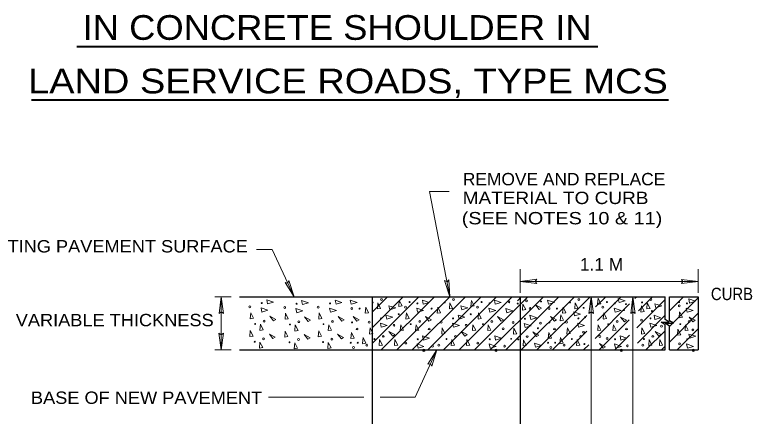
# Model space of a CAD drawing. Extents: x 312583 to 312854, y 144419 to 144597.
# Drawn here: x 312628.97 to 312674.34, y 144455.11 to 144479.79 of the extents above; entities that cross this region are included whole.
import ezdxf
from ezdxf.enums import TextEntityAlignment as Align

# ---------------------------------------------------------------- set-up
doc = ezdxf.new("R2010")
doc.units = 0
doc.header["$LTSCALE"] = 0.3
doc.header["$PDMODE"] = 32
doc.header["$PDSIZE"] = 0.15
doc.layers.add('1', color=7, linetype='Continuous', lineweight=13)

msp = doc.modelspace()

# ---------------------------------------------------------------- linework, layer by layer
at = {"layer": '1', "lineweight": 40}
for p, q in [((312632.7943, 144477.8512), (312664.8483, 144477.8512)), ((312629.9918, 144474.5584), (312669.1922, 144474.5584))]:
    msp.add_line(p, q, dxfattribs=at)
at = {"layer": '1'}
for p, q in [((312644.8091, 144465.3641), (312643.8508, 144465.3641)), ((312644.8091, 144465.3641), (312646.1585, 144462.4584)), ((312660.0581, 144464.1604), (312660.0581, 144462.6884)), ((312671.0138, 144464.1604), (312671.0138, 144462.6884)), ((312660.0581, 144463.4014), (312671.0138, 144463.4014)), ((312642.2868, 144462.4584), (312641.2748, 144462.4584)), ((312641.6735, 144462.4584), (312641.6735, 144459.1848)), ((312650.9501, 144459.5834), (312653.8251, 144462.4584)), ((312650.9501, 144460.5418), (312652.8668, 144462.4584)), ((312650.9501, 144461.5001), (312651.9085, 144462.4584)), ((312651.5098, 144459.1848), (312654.7835, 144462.4584)), ((312652.4681, 144459.1848), (312655.7418, 144462.4584)), ((312653.4265, 144459.1848), (312656.7001, 144462.4584)), ((312654.3848, 144459.1848), (312657.6585, 144462.4584)), ((312655.3431, 144459.1848), (312658.6168, 144462.4584)), ((312656.3015, 144459.1848), (312659.5751, 144462.4584)), ((312657.2598, 144459.1848), (312660.5335, 144462.4584)), ((312658.2181, 144459.1848), (312661.4918, 144462.4584)), ((312659.1765, 144459.1848), (312662.4501, 144462.4584)), ((312659.8895, 144462.2131), (312660.1348, 144462.4584)), ((312660.1348, 144459.1848), (312663.4085, 144462.4584)), ((312661.0931, 144459.1848), (312664.3668, 144462.4584)), ((312664.4281, 144462.4584), (312664.4281, 144440.1484)), ((312664.6965, 144461.8298), (312665.3251, 144462.4584)), ((312664.8191, 144460.9941), (312666.2835, 144462.4584)), ((312667.0041, 144462.4584), (312667.0041, 144433.4478)), ((312667.1191, 144462.3434), (312667.2418, 144462.4584)), ((312667.2495, 144460.5494), (312668.9821, 144462.2821)), ((312667.3415, 144461.5998), (312668.2001, 144462.4584)), ((312669.2428, 144461.5844), (312670.1168, 144462.4584)), ((312669.2428, 144460.6261), (312671.0138, 144462.3971)), ((312664.6811, 144459.8978), (312666.7971, 144462.0138)), ((312662.0515, 144459.1848), (312664.1675, 144461.3084)), ((312667.2725, 144459.6141), (312668.9821, 144461.3238)), ((312669.2428, 144459.6678), (312671.0138, 144461.4388)), ((312664.9265, 144459.1848), (312666.7741, 144461.0324)), ((312667.8015, 144459.1848), (312668.9821, 144460.3654)), ((312669.7181, 144459.1848), (312671.0138, 144460.4804)), ((312663.0098, 144459.1848), (312664.1598, 144460.3348)), ((312665.8848, 144459.1848), (312666.7971, 144460.1048)), ((312663.9681, 144459.1848), (312664.2825, 144459.4991)), ((312642.2868, 144459.1848), (312641.2748, 144459.1848)), ((312653.5951, 144456.2791), (312654.9445, 144459.1848)), ((312668.7598, 144459.1848), (312668.9591, 144459.3918)), ((312650.4365, 144456.2791), (312644.5868, 144456.2791)), ((312653.5951, 144456.2791), (312651.4485, 144456.2791))]:
    msp.add_line(p, q, dxfattribs=at)
at = {"layer": '1', "lineweight": 25}
for p, q in [((312642.8005, 144462.4584), (312668.9821, 144462.4584)), ((312646.1585, 144462.4584), (312661.0165, 144462.4584)), ((312650.9501, 144462.4584), (312650.9501, 144433.4478)), ((312660.0581, 144462.4584), (312660.0581, 144459.1848)), ((312669.2428, 144462.4584), (312671.0138, 144462.4584)), ((312671.0138, 144462.4584), (312671.0138, 144459.1848)), ((312642.8005, 144459.1848), (312649.4321, 144459.1848)), ((312649.4321, 144459.1848), (312668.9821, 144459.1848)), ((312660.0581, 144459.1848), (312660.0581, 144433.4478)), ((312669.2428, 144459.1848), (312671.0138, 144459.1848))]:
    msp.add_line(p, q, dxfattribs=at)
at = {"layer": '1'}
for points in [[(312655.6958, 144468.9214), (312654.4921, 144468.9214), (312655.7418, 144462.4584)], [(312652.5985, 144461.8681), (312652.6215, 144462.2361), (312652.7978, 144461.8988), (312652.5985, 144461.8604)], [(312657.0298, 144461.8681), (312657.0605, 144462.2361), (312657.2291, 144461.8988), (312657.0298, 144461.8604)], [(312664.8268, 144461.9984), (312664.8575, 144462.3664), (312665.0261, 144462.0214), (312664.8268, 144461.9908)], [(312650.5285, 144461.4464), (312650.5591, 144461.8144), (312650.7278, 144461.4771), (312650.5361, 144461.4388)], [(312651.2798, 144461.7148), (312651.3028, 144462.0828), (312651.4791, 144461.7454), (312651.2798, 144461.7071)], [(312654.9675, 144461.4464), (312654.9981, 144461.8144), (312655.1668, 144461.4771), (312654.9675, 144461.4388)], [(312655.7111, 144461.7148), (312655.7418, 144462.0828), (312655.9105, 144461.7454), (312655.7111, 144461.7071)], [(312660.2038, 144461.6381), (312660.2345, 144462.0061), (312660.4031, 144461.6688), (312660.2038, 144461.6304)], [(312662.6725, 144461.4464), (312662.7031, 144461.8144), (312662.8718, 144461.4771), (312662.6801, 144461.4388)], [(312663.4238, 144461.7148), (312663.4468, 144462.0828), (312663.6231, 144461.7454), (312663.4238, 144461.7071)], [(312667.4948, 144461.5231), (312667.5255, 144461.8911), (312667.6941, 144461.5461), (312667.4948, 144461.5154)], [(312667.8551, 144461.7148), (312667.8858, 144462.0828), (312668.0545, 144461.7454), (312667.8551, 144461.7071)], [(312647.6688, 144461.0938), (312647.6995, 144461.4618), (312647.8681, 144461.1168), (312647.6688, 144461.0861)], [(312653.0355, 144461.0938), (312653.0661, 144461.4618), (312653.2348, 144461.1168), (312653.0355, 144461.0861)], [(312657.4745, 144461.0938), (312657.4975, 144461.4618), (312657.6661, 144461.1168), (312657.4745, 144461.0861)], [(312665.1795, 144461.0938), (312665.2101, 144461.4618), (312665.3788, 144461.1168), (312665.1795, 144461.0861)], [(312669.8408, 144461.1628), (312669.8715, 144461.5308), (312670.0401, 144461.1934), (312669.8485, 144461.1551)], [(312644.0501, 144460.3961), (312644.0808, 144460.7641), (312644.2495, 144460.4268), (312644.0578, 144460.3884)], [(312646.1968, 144460.3578), (312646.2275, 144460.7258), (312646.3961, 144460.3884), (312646.1968, 144460.3501)], [(312647.6381, 144459.9974), (312647.6688, 144460.3654), (312647.8375, 144460.0281), (312647.6381, 144459.9898)], [(312650.7968, 144460.1738), (312650.8275, 144460.5418), (312650.9961, 144460.2044), (312650.7968, 144460.1661)], [(312655.2358, 144460.1738), (312655.2665, 144460.5418), (312655.4351, 144460.2044), (312655.2358, 144460.1661)], [(312659.6518, 144460.1584), (312659.6825, 144460.5188), (312659.8511, 144460.1814), (312659.6518, 144460.1508)], [(312662.9408, 144460.1738), (312662.9715, 144460.5418), (312663.1401, 144460.2044), (312662.9408, 144460.1661)], [(312667.5255, 144460.1738), (312667.5561, 144460.5418), (312667.7248, 144460.2044), (312667.5255, 144460.1661)], [(312669.7488, 144460.0971), (312669.7718, 144460.4651), (312669.9481, 144460.1201), (312669.7488, 144460.0894)], [(312649.6468, 144459.8978), (312649.6775, 144460.2581), (312649.8461, 144459.9208), (312649.6468, 144459.8901)], [(312650.3675, 144459.5758), (312650.3981, 144459.9438), (312650.5668, 144459.5988), (312650.3675, 144459.5681)], [(312661.7908, 144459.8978), (312661.8215, 144460.2581), (312661.9901, 144459.9208), (312661.7908, 144459.8901)], [(312662.5115, 144459.5758), (312662.5421, 144459.9438), (312662.7108, 144459.5988), (312662.5115, 144459.5681)], [(312644.0271, 144459.2998), (312644.0578, 144459.6678), (312644.2265, 144459.3304), (312644.0271, 144459.2921)], [(312646.1661, 144459.2614), (312646.1968, 144459.6294), (312646.3655, 144459.2921), (312646.1661, 144459.2538)], [(312648.2361, 144459.2844), (312648.2591, 144459.6448), (312648.4278, 144459.3074), (312648.2361, 144459.2768)], [(312651.3948, 144459.4608), (312651.4178, 144459.8288), (312651.5865, 144459.4838), (312651.3948, 144459.4531)], [(312652.3301, 144459.4608), (312652.3608, 144459.8211), (312652.5295, 144459.4838), (312652.3301, 144459.4531)], [(312655.8261, 144459.4608), (312655.8568, 144459.8288), (312656.0255, 144459.4838), (312655.8261, 144459.4531)], [(312656.7615, 144459.4608), (312656.7921, 144459.8211), (312656.9608, 144459.4838), (312656.7615, 144459.4531)], [(312663.5388, 144459.4608), (312663.5618, 144459.8288), (312663.7305, 144459.4838), (312663.5388, 144459.4531)], [(312667.9701, 144459.4608), (312668.0008, 144459.8288), (312668.1695, 144459.4838), (312667.9701, 144459.4531)], [(312668.6295, 144459.4608), (312668.6525, 144459.8211), (312668.8211, 144459.4838), (312668.6295, 144459.4531)]]:
    msp.add_lwpolyline(points, dxfattribs=at)
for points in [[(312661.0931, 144463.2711), (312660.0581, 144463.4014), (312661.0931, 144463.5394), (312660.9858, 144463.4014)], [(312669.9788, 144463.5241), (312671.0138, 144463.4014), (312669.9788, 144463.2634), (312670.0785, 144463.4014)], [(312645.8365, 144463.4551), (312646.1585, 144462.4584), (312645.5988, 144463.3401), (312645.7675, 144463.3018)], [(312655.6651, 144463.5011), (312655.7418, 144462.4584), (312655.4121, 144463.4474), (312655.5655, 144463.3784)], [(312641.5508, 144461.4234), (312641.6735, 144462.4584), (312641.8115, 144461.4234), (312641.6735, 144461.5308)], [(312644.4718, 144462.2668), (312644.5255, 144462.0138), (312644.8935, 144462.1288)], [(312646.6108, 144462.2284), (312646.6645, 144461.9754), (312647.0325, 144462.0904)], [(312648.6731, 144462.2514), (312648.7345, 144461.9984), (312649.1025, 144462.1058)], [(312649.6085, 144462.2514), (312649.6621, 144461.9984), (312650.0301, 144462.1058)], [(312654.0475, 144462.2514), (312654.1011, 144461.9984), (312654.4691, 144462.1058)], [(312658.4788, 144462.2514), (312658.5325, 144461.9984), (312658.9005, 144462.1058)], [(312661.7525, 144462.2514), (312661.8061, 144461.9984), (312662.1741, 144462.1058)], [(312664.2978, 144461.4234), (312664.4281, 144462.4584), (312664.5661, 144461.4234), (312664.4281, 144461.5308)], [(312666.0918, 144462.3588), (312666.1455, 144462.1058), (312666.5135, 144462.2131)], [(312666.8815, 144461.4234), (312667.0041, 144462.4584), (312667.1421, 144461.4234), (312667.0041, 144461.5308)], [(312670.4311, 144462.3204), (312670.4848, 144462.0674), (312670.8528, 144462.1824)], [(312644.1268, 144461.7684), (312644.1805, 144461.5154), (312644.5485, 144461.6304)], [(312646.2658, 144461.7301), (312646.3271, 144461.4771), (312646.6951, 144461.5921)], [(312648.3358, 144461.7531), (312648.3895, 144461.5001), (312648.7575, 144461.6074)], [(312651.9775, 144461.9064), (312652.0388, 144461.6534), (312652.4068, 144461.7684)], [(312653.7025, 144461.7531), (312653.7561, 144461.5001), (312654.1241, 144461.6074)], [(312656.4165, 144461.9064), (312656.4701, 144461.6534), (312656.8381, 144461.7684)], [(312658.1338, 144461.7531), (312658.1951, 144461.5001), (312658.5631, 144461.6074)], [(312659.1841, 144461.7378), (312659.2455, 144461.4771), (312659.6135, 144461.5921)], [(312661.3691, 144461.7531), (312661.0011, 144461.9524), (312661.2235, 144461.6688)], [(312665.8465, 144461.7531), (312665.9001, 144461.5001), (312666.2681, 144461.6074)], [(312668.3458, 144462.0291), (312668.4071, 144461.7761), (312668.7751, 144461.8911)], [(312670.2778, 144461.7531), (312670.3391, 144461.5001), (312670.7071, 144461.6074)], [(312643.4598, 144461.1091), (312643.4905, 144461.4771), (312643.6591, 144461.1398)], [(312645.0238, 144461.0631), (312644.6558, 144461.2624), (312644.8858, 144460.9788)], [(312645.6065, 144461.0708), (312645.6295, 144461.4388), (312645.7981, 144461.1014)], [(312651.8088, 144461.3314), (312651.8625, 144461.0784), (312652.2305, 144461.1934)], [(312656.2401, 144461.3314), (312656.3015, 144461.0784), (312656.6695, 144461.1934)], [(312660.6561, 144461.3161), (312660.7175, 144461.0554), (312661.0855, 144461.1704)], [(312662.5268, 144460.9864), (312662.5575, 144461.3544), (312662.7261, 144461.0171)], [(312663.3625, 144461.5384), (312663.4161, 144461.2778), (312663.7841, 144461.3928)], [(312668.2998, 144461.3161), (312668.3535, 144461.0631), (312668.7215, 144461.1704)], [(312647.1628, 144461.0248), (312646.7948, 144461.2241), (312647.0248, 144460.9404)], [(312649.2328, 144461.0478), (312648.8648, 144461.2394), (312649.0871, 144460.9634)], [(312650.1605, 144461.0478), (312649.7925, 144461.2394), (312650.0225, 144460.9634)], [(312651.4638, 144460.8331), (312651.5175, 144460.5801), (312651.8855, 144460.6951)], [(312654.5995, 144461.0478), (312654.2315, 144461.2394), (312654.4538, 144460.9634)], [(312655.9028, 144460.8331), (312655.9565, 144460.5801), (312656.3245, 144460.6951)], [(312659.0308, 144461.0478), (312658.6628, 144461.2394), (312658.8928, 144460.9634)], [(312660.3188, 144460.8178), (312660.3725, 144460.5571), (312660.7405, 144460.6721)], [(312662.3045, 144461.0478), (312661.9365, 144461.2394), (312662.1665, 144460.9634)], [(312663.6078, 144460.8331), (312663.6615, 144460.5801), (312664.0295, 144460.6951)], [(312666.6131, 144461.0171), (312666.2451, 144461.2088), (312666.4751, 144460.9251)], [(312668.0468, 144460.8331), (312668.1005, 144460.5801), (312668.4685, 144460.6951)], [(312670.8298, 144461.0094), (312670.4618, 144461.2011), (312670.6918, 144460.9251)], [(312643.4368, 144460.0128), (312643.4598, 144460.3808), (312643.6361, 144460.0434)], [(312645.5758, 144459.9744), (312645.6065, 144460.3424), (312645.7751, 144460.0051)], [(312648.2591, 144460.3731), (312648.2898, 144460.7411), (312648.4585, 144460.4038)], [(312652.6905, 144460.3731), (312652.7211, 144460.7411), (312652.8898, 144460.4038)], [(312653.6258, 144460.3731), (312653.6565, 144460.7411), (312653.8251, 144460.4038)], [(312657.1295, 144460.3731), (312657.1525, 144460.7411), (312657.3288, 144460.4038)], [(312658.0648, 144460.3731), (312658.0955, 144460.7411), (312658.2641, 144460.4038)], [(312664.8345, 144460.3731), (312664.8651, 144460.7411), (312665.0338, 144460.4038)], [(312665.7698, 144460.3731), (312665.8005, 144460.7411), (312665.9691, 144460.4038)], [(312670.2088, 144460.3731), (312670.2395, 144460.7411), (312670.4081, 144460.4038)], [(312641.8038, 144460.2198), (312641.6735, 144459.1848), (312641.5355, 144460.2198), (312641.6735, 144460.1201)], [(312645.0008, 144459.9668), (312644.6328, 144460.1661), (312644.8551, 144459.8824)], [(312647.1398, 144459.9284), (312646.7718, 144460.1278), (312646.9941, 144459.8441)], [(312649.2021, 144459.9514), (312648.8341, 144460.1508), (312649.0641, 144459.8671)], [(312652.3608, 144460.1278), (312651.9928, 144460.3271), (312652.2228, 144460.0434)], [(312654.0628, 144460.0511), (312654.1165, 144459.7981), (312654.4845, 144459.9054)], [(312656.7998, 144460.1278), (312656.4318, 144460.3271), (312656.6541, 144460.0434)], [(312658.5018, 144460.0511), (312658.5555, 144459.7981), (312658.9235, 144459.9054)], [(312661.2158, 144460.1048), (312660.8478, 144460.3041), (312661.0701, 144460.0204)], [(312666.2068, 144460.0511), (312666.2605, 144459.7981), (312666.6285, 144459.9054)], [(312668.7291, 144460.1278), (312668.3611, 144460.3271), (312668.5911, 144460.0434)], [(312670.4388, 144460.1661), (312670.5001, 144459.9131), (312670.8681, 144460.0281)], [(312653.7178, 144459.5528), (312653.7791, 144459.2998), (312654.1471, 144459.4071)], [(312658.1568, 144459.5528), (312658.2105, 144459.2998), (312658.5785, 144459.4071)], [(312660.2421, 144459.4378), (312660.2728, 144459.8058), (312660.4415, 144459.4684)], [(312660.9475, 144459.6141), (312661.0011, 144459.3534), (312661.3691, 144459.4684)], [(312665.3098, 144459.3841), (312664.9418, 144459.5834), (312665.1641, 144459.2998)], [(312665.8618, 144459.5528), (312665.9231, 144459.2998), (312666.2911, 144459.4071)], [(312670.3008, 144459.5528), (312670.3545, 144459.2998), (312670.7225, 144459.4071)], [(312654.6225, 144458.1958), (312654.9445, 144459.1848), (312654.3848, 144458.3108), (312654.5535, 144458.3414)]]:
    msp.add_lwpolyline(points, close=True, dxfattribs=at)
at = {"layer": '1', "lineweight": 25}
for points in [[(312668.9821, 144459.1848), (312668.9821, 144460.7334), (312668.7291, 144460.9021), (312669.2351, 144460.9021), (312668.9821, 144461.0631), (312668.9821, 144462.4584)], [(312669.2428, 144459.1848), (312669.2428, 144460.6568), (312668.9898, 144460.8254), (312669.4958, 144460.8254), (312669.2428, 144460.9864), (312669.2428, 144462.4584)]]:
    msp.add_lwpolyline(points, dxfattribs=at)
at = {"layer": '1'}
for centre, radius in [((312651.5309, 144462.2802), 0.0565), ((312653.2588, 144462.1288), 0.0288), ((312655.966, 144462.2802), 0.0565), ((312657.6939, 144462.1288), 0.0288), ((312659.3768, 144462.1384), 0.0565), ((312660.4587, 144462.2035), 0.0565), ((312661.3461, 144462.1671), 0.0288), ((312663.6749, 144462.2802), 0.0565), ((312665.4028, 144462.1288), 0.0288), ((312668.1101, 144462.2802), 0.0565), ((312669.8379, 144462.1288), 0.0288), ((312643.4349, 144461.8326), 0.0565), ((312644.1651, 144462.0665), 0.0288), ((312645.5768, 144461.7943), 0.0565), ((312646.307, 144462.0281), 0.0288), ((312647.641, 144461.8135), 0.0565), ((312648.3713, 144462.0473), 0.0288), ((312649.6976, 144461.7301), 0.0565), ((312650.1815, 144461.7272), 0.0288), ((312650.9837, 144462.1096), 0.0288), ((312653.0096, 144461.8135), 0.0565), ((312653.7398, 144462.0473), 0.0288), ((312654.6167, 144461.7272), 0.0288), ((312655.4188, 144462.1096), 0.0288), ((312657.4448, 144461.8135), 0.0565), ((312658.175, 144462.0473), 0.0288), ((312659.9115, 144462.0329), 0.0288), ((312660.6686, 144461.7445), 0.0565), ((312661.8416, 144461.7301), 0.0565), ((312662.3256, 144461.7272), 0.0288), ((312663.1277, 144462.1096), 0.0288), ((312663.9691, 144461.778), 0.0288), ((312665.1536, 144461.8135), 0.0565), ((312665.8838, 144462.0473), 0.0288), ((312666.57, 144462.0032), 0.0288), ((312667.5628, 144462.1096), 0.0288), ((312669.8533, 144461.9016), 0.0565), ((312670.319, 144462.0473), 0.0288), ((312652.5898, 144461.3832), 0.0288), ((312657.025, 144461.3832), 0.0288), ((312666.4502, 144461.641), 0.0288), ((312668.1656, 144461.5777), 0.0288), ((312643.7598, 144460.79), 0.0288), ((312644.307, 144460.9606), 0.0565), ((312646.4488, 144460.9222), 0.0565), ((312647.9659, 144460.7708), 0.0288), ((312648.5131, 144460.9414), 0.0565), ((312649.7187, 144460.8801), 0.0288), ((312650.7728, 144460.8954), 0.0565), ((312651.5031, 144461.1292), 0.0288), ((312653.3345, 144460.7708), 0.0288), ((312653.8817, 144460.9414), 0.0565), ((312655.208, 144460.8954), 0.0565), ((312655.9383, 144461.1292), 0.0288), ((312657.7696, 144460.7708), 0.0288), ((312658.3168, 144460.9414), 0.0565), ((312659.625, 144460.8762), 0.0565), ((312660.3552, 144461.1101), 0.0288), ((312661.3068, 144460.8379), 0.0565), ((312661.8627, 144460.8801), 0.0288), ((312662.9168, 144460.8954), 0.0565), ((312663.6471, 144461.1292), 0.0288), ((312664.0544, 144461.1992), 0.0288), ((312665.4785, 144460.7708), 0.0288), ((312666.0257, 144460.9414), 0.0565), ((312667.5341, 144461.0133), 0.0565), ((312668.0823, 144461.1292), 0.0288), ((312669.9136, 144460.7708), 0.0288), ((312670.4608, 144460.9414), 0.0565), ((312645.9016, 144460.7516), 0.0288), ((312650.0273, 144460.4747), 0.0565), ((312652.3023, 144460.7037), 0.0565), ((312654.4624, 144460.4747), 0.0565), ((312656.7375, 144460.7037), 0.0565), ((312659.0136, 144460.4939), 0.0565), ((312661.1583, 144460.5169), 0.0288), ((312662.1713, 144460.4747), 0.0565), ((312666.6064, 144460.4747), 0.0565), ((312668.7579, 144460.651), 0.0565), ((312670.6947, 144460.4162), 0.0565), ((312644.2801, 144459.8652), 0.0565), ((312648.4863, 144459.846), 0.0565), ((312651.6449, 144460.0233), 0.0565), ((312656.0801, 144460.0233), 0.0565), ((312659.5109, 144459.8719), 0.0288), ((312660.4971, 144460.0041), 0.0565), ((312663.7889, 144460.0233), 0.0565), ((312663.9566, 144460.2706), 0.0565), ((312664.9638, 144460.0137), 0.0565), ((312665.4085, 144459.8911), 0.0565), ((312668.2241, 144460.0233), 0.0565), ((312643.7329, 144459.6946), 0.0288), ((312645.8748, 144459.6563), 0.0288), ((312646.422, 144459.8269), 0.0565), ((312647.939, 144459.6754), 0.0288), ((312649.6391, 144459.6285), 0.0288), ((312650.0713, 144459.6285), 0.0288), ((312650.6205, 144459.4799), 0.0565), ((312651.0977, 144459.8527), 0.0288), ((312653.0288, 144459.6131), 0.0565), ((312653.759, 144459.847), 0.0288), ((312654.6742, 144459.4224), 0.0565), ((312655.0556, 144459.4799), 0.0565), ((312655.5329, 144459.8527), 0.0288), ((312657.4639, 144459.6131), 0.0565), ((312658.1942, 144459.847), 0.0288), ((312659.1094, 144459.4224), 0.0565), ((312659.9498, 144459.8336), 0.0288), ((312661.7831, 144459.6285), 0.0288), ((312662.2153, 144459.6285), 0.0288), ((312662.7645, 144459.4799), 0.0565), ((312663.2417, 144459.8527), 0.0288), ((312664.016, 144459.5508), 0.0288), ((312665.903, 144459.847), 0.0288), ((312666.6572, 144459.4435), 0.0565), ((312667.606, 144459.4799), 0.0565), ((312667.6769, 144459.8527), 0.0288), ((312669.8724, 144459.5604), 0.0565), ((312670.3382, 144459.847), 0.0288), ((312649.8097, 144459.3391), 0.0565), ((312661.9537, 144459.3391), 0.0565)]:
    msp.add_circle(centre, radius, dxfattribs=at)
for p in [(312654.1395, 144459.1694), (312658.5785, 144459.1694), (312666.2835, 144459.1694), (312670.7225, 144459.1694)]:
    msp.add_point(p, dxfattribs=at)

# ---------------------------------------------------------------- texts
for s, width, p in [('IN CONCRETE SHOULDER IN', 1.1, (312648.8038, 144478.2522)), ('LAND SERVICE ROADS, TYPE MCS', 1.15, (312649.4673, 144474.9595))]:
    msp.add_text(s, height=1.52, dxfattribs=dict(at, width=width)).set_placement(p, align=Align.CENTER)
for s, width, p in [('REMOVE AND REPLACE', 1.05, (312656.5381, 144469.3088)), ('MATERIAL TO CURB', 1.15, (312656.5268, 144468.1557)), ('(SEE NOTES 10 & 11)', 1.2, (312656.4708, 144466.9083)), ('EXISTING PAVEMENT SURFACE', 1.1, (312625.9796, 144465.1801)), ('1.1 M', 1.05, (312663.7361, 144464.0708)), ('CURB', 0.9, (312671.7977, 144462.2504)), ('VARIABLE THICKNESS', 1.1, (312629.0331, 144460.6445)), ('BASE OF NEW PAVEMENT', 1.1, (312629.9691, 144455.8704))]:
    msp.add_text(s, height=0.76, dxfattribs=dict(at, width=width)).set_placement(p)

doc.saveas('drawing.dxf')
